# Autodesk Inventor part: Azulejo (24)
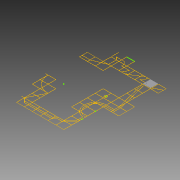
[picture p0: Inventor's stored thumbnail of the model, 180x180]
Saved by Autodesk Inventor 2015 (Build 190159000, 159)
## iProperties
Created: 2015-04
Part Number: Azulejo (24)
Material: Genérico
Document SubType Name: Modeling
Designer: Felipe
Density: 1 g/cm^3
Appearance: Padrão
Author: Felipe
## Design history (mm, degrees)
sketch "Sketch1"
  geometry: L1 (-1510, -7490)-(-1510, -6010); L2 (992.445, 7510)-(992.445, 8990); L3 (1012.445, 7510)-(1012.445, 8990); L4 (-3010, -1490)-(-3010, -10); L5 (-1510, 7490)-(-2990, 7490); L6 (-2990, 10)-(-1510, 10); L7 (-1510, -10)-(-2990, -10); L8 (-1510, -1490)-(-1510, -10); L9 (-10, 9010)-(-10, 10490); L10 (-10, 7510)-(-10, 8990); L11 (-10, 7490)-(-1490, 7490); L12 (-1490, 6010)-(-10, 6010); L13 (-10, 5990)-(-1490, 5990); L14 (-1490, -10)-(-1490, -1490); L15 (-1490, -1490)-(-10, -1490); L16 (-10, -1510)-(-1490, -1510); L17 (-10, -2990)-(-10, -1510); L18 (-10, -5990)-(-10, -4510); L19 (-1490, -7490)-(-10, -7490); L20 (10, 8990)-(10, 7510); L21 (1490, 7510)-(1490, 8990); L22 (10, 6010)-(1490, 6010); L23 (1490, 6010)-(1490, 7490); L24 (1490, 5990)-(10, 5990); L25 (4490, -6010)-(3010, -6010); L26 (10, -1510)-(10, -2990); L27 (10, -3010)-(10, -4490); L28 (10, -4510)-(10, -5990); L29 (10, -5990)-(1490, -5990); L30 (1490, -6010)-(10, -6010); L31 (10, -7490)-(1490, -7490); L32 (2990, 9010)-(2990, 10490); L33 (1510, 8990)-(1510, 7510); L34 (1510, 7510)-(2990, 7510); L35 (2990, 7490)-(1510, 7490); L36 (1510, 7490)-(1510, 6010); L37 (1510, -5990)-(2990, -5990); L38 (2990, -6010)-(1510, -6010); L39 (1510, -7490)-(2990, -7490); L40 (3010, 10490)-(3010, 9010); L41 (3010, 9010)-(4490, 9010); L42 (4490, 8990)-(3010, 8990); L43 (4490, 7490)-(3010, 7490); L44 (4490, 1510)-(4490, 2990); L45 (4490, 10)-(4490, 1490); L46 (4490, -1490)-(4490, -10); L47 (4490, -2990)-(4490, -1510); L48 (3010, -5990)-(4490, -5990); L49 (3010, -7490)-(4490, -7490); L50 (4510, 9010)-(5990, 9010); L51 (5990, 8990)-(4510, 8990); L52 (4510, 7510)-(5990, 7510); L53 (5990, 7490)-(4510, 7490); L54 (4510, 3010)-(5990, 3010); L55 (5990, 2990)-(4510, 2990); L56 (4510, 2990)-(4510, 1510); L57 (4510, 1510)-(5990, 1510); L58 (5990, 1510)-(5990, 1740.185); L59 (5990, 1760.2)-(5990, 2259.8); L60 (5990, 2279.815)-(5990, 2990); L61 (5990, 1490)-(4510, 1490); L62 (4510, 1490)-(4510, 10); L63 (4510, 10)-(5990, 10); L64 (5990, 10)-(5990, 1490)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; A1 r 250 centre (6000, 2010) between (5990, 2259.8) and (5990, 1760.2); A2 r 250 centre (6000, 2010) between (6010, 1760.2) and (6010, 2259.8); A3 r 270 centre (6000, 2010) between (5990, 2279.815) and (5990, 1740.185); A4 r 270 centre (6000, 2010) between (6010, 1740.185) and (6010, 2279.815); A5 r 3010.017 centre (0, 0) between (-1490, -2615.358) and (-346.554, -2990); A6 r 2990.017 centre (0, 0) between (-1490, -2592.316) and (-10, -2990); A7 r 3010.017 centre (0, 0) between (-2603.863, -1510) and (-1510, -2603.863); A8 r 2990.017 centre (0, 0) between (-2580.717, -1510) and (-1510, -2580.717); A9 r 3010.017 centre (0, 0) between (-2990, -346.554) and (-2615.358, -1490); A10 r 2990.017 centre (0, 0) between (-2990, -10) and (-2592.316, -1490); A11 r 2131.367 centre (7500, -1500) between (7490, 631.344) and (6010, 24.017); A12 r 2131.367 centre (7500, -1500) between (5975.983, -10) and (5368.656, -1490); A13 r 2131.367 centre (7500, -1500) between (5368.656, -1510) and (5975.983, -2990); A14 r 2131.367 centre (7500, -1500) between (6010, -3024.017) and (7190, -3608.703); A15 r 1831.367 centre (7500, -1500) between (7490.321, 331.342) and (6463.753, 10); A16 r 1831.367 centre (7500, -1500) between (6435.196, -10) and (6010, -435.196); A17 r 1831.367 centre (7500, -1500) between (5990, -463.753) and (5668.66, -1490); A18 r 1831.367 centre (7500, -1500) between (5668.66, -1510) and (5990, -2536.247); A19 r 1831.367 centre (7500, -1500) between (6010, -2564.804) and (6435.196, -2990); A20 r 1831.367 centre (7500, -1500) between (6463.753, -3010) and (7490, -3331.34); A21 r 2111.367 centre (7500, -1500) between (7490.047, 611.344) and (6024.272, 10); A22 r 2111.367 centre (7500, -1500) between (5990, -24.272) and (5388.656, -1490); A23 r 2111.367 centre (7500, -1500) between (5388.656, -1510) and (5990, -2975.728); A24 r 2111.367 centre (7500, -1500) between (6024.272, -3010) and (7210, -3591.357); A25 r 1811.367 centre (7500, -1500) between (7490.374, 311.342) and (6499.524, 10); A26 r 1811.367 centre (7500, -1500) between (6469.975, -10) and (6010, -469.975); A27 r 1811.367 centre (7500, -1500) between (5990, -499.524) and (5688.66, -1490); A28 r 1811.367 centre (7500, -1500) between (5688.66, -1510) and (5990, -2500.476); A29 r 1811.367 centre (7500, -1500) between (6010, -2530.025) and (6469.975, -2990); A30 r 1811.367 centre (7500, -1500) between (6499.524, -3010) and (7490, -3311.34); A31 r 449.871 centre (7499.449, -4060.672) between (7510, -4510.419) and (7521.546, -4510); 6 further points
  constraints: 1042 end point, 64 point on circle, 31 centre point, 13 point on line, 1 horizontal, 1 other
extrude "Extrusion1" new body sketch "Sketch1" distance "d0" = 60; taper "d1" = 0 deg
extrude "Extrusion2" new body sketch "Sketch1" distance "d2" = 60; taper "d3" = 0 deg
extrude "Extrusion3" new body sketch "Sketch1" distance "d4" = 60; taper "d5" = 0 deg
body "Solid1"
body "Solid2"
body "Solid3"
